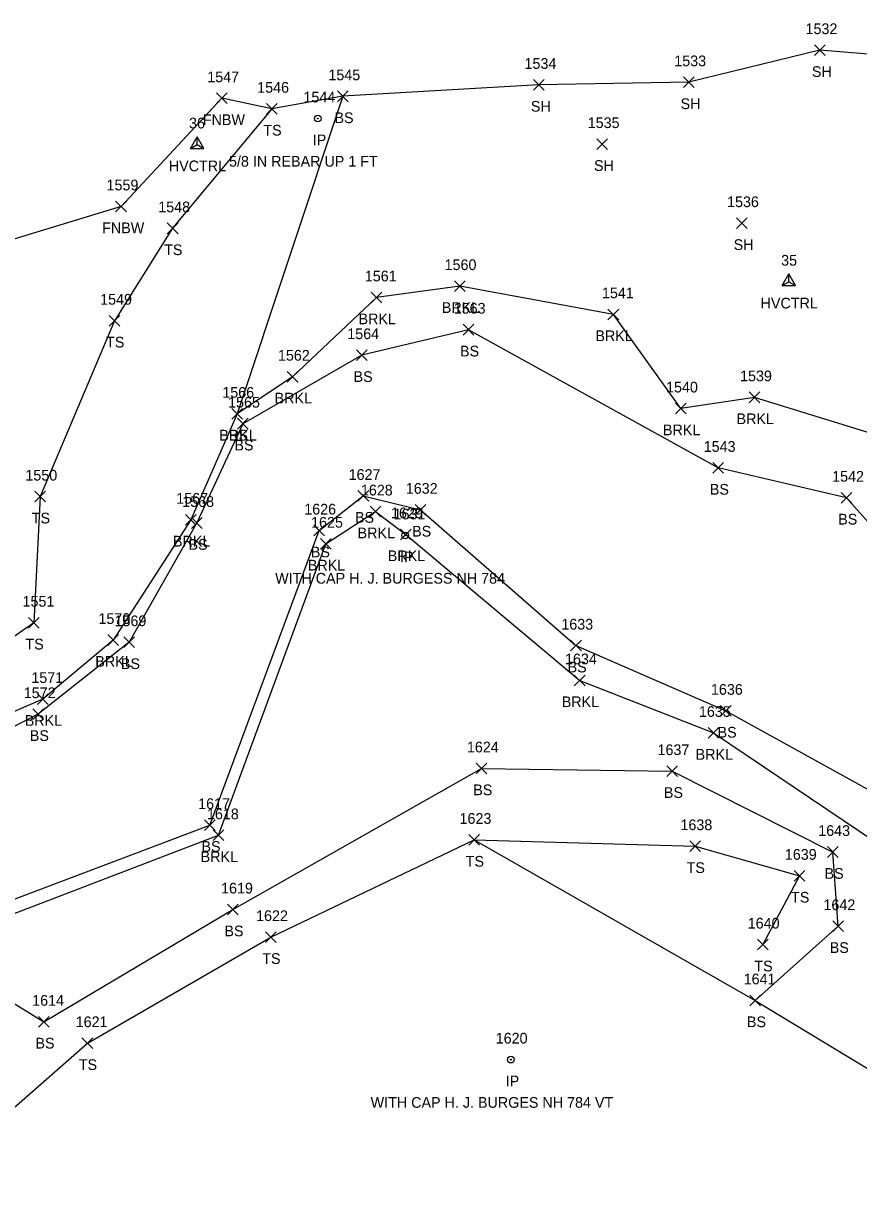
# Model space of a CAD drawing. Extents: x 1754529 to 1755810, y 621660 to 624656.
# Drawn here: x 1754679.8 to 1754836, y 624163.7 to 624380.7 of the extents above; entities that cross this region are included whole.
import ezdxf

# ---------------------------------------------------------------- set-up
doc = ezdxf.new("R2010")
doc.units = 0
for name, color, linetype in [('C_A', 7, 'Continuous'), ('C_I', 7, 'Continuous'), ('CPSM', 7, 'Continuous'), ('L_A', 7, 'Continuous'), ('L_I', 7, 'Continuous'), ('L_TIC', 7, 'Continuous'), ('LAWE', 7, 'Continuous'), ('LELB', 7, 'Continuous'), ('LSOGP', 7, 'Continuous'), ('M_A', 7, 'Continuous'), ('M_C', 7, 'Continuous'), ('M_I', 7, 'Continuous'), ('MPIR', 7, 'Continuous')]:
    doc.layers.add(name, color=color, linetype=linetype)

msp = doc.modelspace()

# ---------------------------------------------------------------- linework, layer by layer
at = {"layer": 'CPSM'}
for p, q in [((1754711.07, 624357.33), (1754712.32, 624359.5)), ((1754713.57, 624357.33), (1754712.32, 624359.5)), ((1754712.32, 624358.05), (1754712.32, 624359.5)), ((1754711.07, 624357.33), (1754712.32, 624358.05)), ((1754711.07, 624357.33), (1754713.57, 624357.33)), ((1754712.32, 624358.05), (1754712.32, 624358.05)), ((1754712.32, 624358.05), (1754713.57, 624357.33)), ((1754821.66, 624331.7), (1754822.91, 624333.86)), ((1754824.16, 624331.7), (1754822.91, 624333.86)), ((1754822.91, 624332.42), (1754822.91, 624333.86)), ((1754821.66, 624331.7), (1754822.91, 624332.42)), ((1754821.66, 624331.7), (1754824.16, 624331.7)), ((1754822.91, 624332.42), (1754822.91, 624332.42)), ((1754822.91, 624332.42), (1754824.16, 624331.7))]:
    msp.add_line(p, q, dxfattribs=at)
at = {"layer": 'L_TIC'}
for points in [[(1754827.7, 624374.67), (1754829.7, 624376.67)], [(1754829.7, 624374.67), (1754827.7, 624376.67)], [(1754775.19, 624368.18), (1754777.19, 624370.18)], [(1754777.19, 624368.18), (1754775.19, 624370.18)], [(1754803.17, 624368.67), (1754805.17, 624370.67)], [(1754805.17, 624368.67), (1754803.17, 624370.67)], [(1754738.54, 624366.05), (1754740.54, 624368.05)], [(1754740.54, 624366.05), (1754738.54, 624368.05)], [(1754715.91, 624365.68), (1754717.91, 624367.68)], [(1754717.91, 624365.68), (1754715.91, 624367.68)], [(1754725.29, 624363.72), (1754727.29, 624365.72)], [(1754727.29, 624363.72), (1754725.29, 624365.72)], [(1754786.99, 624357.12), (1754788.99, 624359.12)], [(1754788.99, 624357.12), (1754786.99, 624359.12)], [(1754697.09, 624345.48), (1754699.09, 624347.48)], [(1754699.09, 624345.48), (1754697.09, 624347.48)], [(1754813.09, 624342.35), (1754815.09, 624344.35)], [(1754815.09, 624342.35), (1754813.09, 624344.35)], [(1754706.74, 624341.39), (1754708.74, 624343.39)], [(1754708.74, 624341.39), (1754706.74, 624343.39)], [(1754760.39, 624330.59), (1754762.39, 624332.59)], [(1754762.39, 624330.59), (1754760.39, 624332.59)], [(1754744.82, 624328.48), (1754746.82, 624330.48)], [(1754746.82, 624328.48), (1754744.82, 624330.48)], [(1754789.09, 624325.32), (1754791.09, 624327.32)], [(1754791.09, 624325.32), (1754789.09, 624327.32)], [(1754695.89, 624324.13), (1754697.89, 624326.13)], [(1754697.89, 624324.13), (1754695.89, 624326.13)], [(1754762, 624322.46), (1754764, 624324.46)], [(1754764, 624322.46), (1754762, 624324.46)], [(1754742.11, 624317.69), (1754744.11, 624319.69)], [(1754744.11, 624317.69), (1754742.11, 624319.69)], [(1754729.15, 624313.67), (1754731.15, 624315.67)], [(1754731.15, 624313.67), (1754729.15, 624315.67)], [(1754815.47, 624309.82), (1754817.47, 624311.82)], [(1754817.47, 624309.82), (1754815.47, 624311.82)], [(1754801.72, 624307.73), (1754803.72, 624309.73)], [(1754803.72, 624307.73), (1754801.72, 624309.73)], [(1754718.81, 624306.75), (1754720.81, 624308.75)], [(1754720.81, 624306.75), (1754718.81, 624308.75)], [(1754718.81, 624306.75), (1754720.81, 624308.75)], [(1754720.81, 624306.75), (1754718.81, 624308.75)], [(1754719.84, 624304.9), (1754721.84, 624306.9)], [(1754721.84, 624304.9), (1754719.84, 624306.9)], [(1754808.68, 624296.64), (1754810.68, 624298.64)], [(1754810.68, 624296.64), (1754808.68, 624298.64)], [(1754682, 624291.27), (1754684, 624293.27)], [(1754684, 624291.27), (1754682, 624293.27)], [(1754742.37, 624291.4), (1754744.37, 624293.4)], [(1754744.37, 624291.4), (1754742.37, 624293.4)], [(1754832.67, 624291.06), (1754834.67, 624293.06)], [(1754834.67, 624291.06), (1754832.67, 624293.06)], [(1754744.66, 624288.49), (1754746.66, 624290.49)], [(1754746.66, 624288.49), (1754744.66, 624290.49)], [(1754753.05, 624288.81), (1754755.05, 624290.81)], [(1754755.05, 624288.81), (1754753.05, 624290.81)], [(1754710.15, 624286.95), (1754712.15, 624288.95)], [(1754712.15, 624286.95), (1754710.15, 624288.95)], [(1754711.27, 624286.35), (1754713.27, 624288.35)], [(1754713.27, 624286.35), (1754711.27, 624288.35)], [(1754734.12, 624284.93), (1754736.12, 624286.93)], [(1754736.12, 624284.93), (1754734.12, 624286.93)], [(1754750.29, 624284.22), (1754752.29, 624286.22)], [(1754752.29, 624284.22), (1754750.29, 624286.22)], [(1754735.35, 624282.47), (1754737.35, 624284.47)], [(1754737.35, 624282.47), (1754735.35, 624284.47)], [(1754680.82, 624267.72), (1754682.82, 624269.72)], [(1754682.82, 624267.72), (1754680.82, 624269.72)], [(1754695.65, 624264.49), (1754697.65, 624266.49)], [(1754697.65, 624264.49), (1754695.65, 624266.49)], [(1754698.63, 624264.07), (1754700.63, 624266.07)], [(1754700.63, 624264.07), (1754698.63, 624266.07)], [(1754782.11, 624263.44), (1754784.11, 624265.44)], [(1754784.11, 624263.44), (1754782.11, 624265.44)], [(1754782.8, 624256.95), (1754784.8, 624258.95)], [(1754784.8, 624256.95), (1754782.8, 624258.95)], [(1754682.46, 624253.46), (1754684.46, 624255.46)], [(1754684.46, 624253.46), (1754682.46, 624255.46)], [(1754810.13, 624251.26), (1754812.13, 624253.26)], [(1754812.13, 624251.26), (1754810.13, 624253.26)], [(1754681.61, 624250.63), (1754683.61, 624252.63)], [(1754683.61, 624250.63), (1754681.61, 624252.63)], [(1754807.82, 624247.13), (1754809.82, 624249.13)], [(1754809.82, 624247.13), (1754807.82, 624249.13)], [(1754764.47, 624240.5), (1754766.47, 624242.5)], [(1754766.47, 624240.5), (1754764.47, 624242.5)], [(1754800.09, 624240), (1754802.09, 624242)], [(1754802.09, 624240), (1754800.09, 624242)], [(1754713.68, 624229.92), (1754715.68, 624231.92)], [(1754715.68, 624229.92), (1754713.68, 624231.92)], [(1754715.32, 624228.01), (1754717.32, 624230.01)], [(1754717.32, 624228.01), (1754715.32, 624230.01)], [(1754763.09, 624227.15), (1754765.09, 624229.15)], [(1754765.09, 624227.15), (1754763.09, 624229.15)], [(1754804.37, 624225.97), (1754806.37, 624227.97)], [(1754806.37, 624225.97), (1754804.37, 624227.97)], [(1754830.12, 624224.89), (1754832.12, 624226.89)], [(1754832.12, 624224.89), (1754830.12, 624226.89)], [(1754830.12, 624224.89), (1754832.12, 624226.89)], [(1754832.12, 624224.89), (1754830.12, 624226.89)], [(1754823.89, 624220.44), (1754825.89, 624222.44)], [(1754825.89, 624220.44), (1754823.89, 624222.44)], [(1754717.97, 624214.14), (1754719.97, 624216.14)], [(1754719.97, 624214.14), (1754717.97, 624216.14)], [(1754831.09, 624211.03), (1754833.09, 624213.03)], [(1754833.09, 624211.03), (1754831.09, 624213.03)], [(1754725.07, 624208.99), (1754727.07, 624210.99)], [(1754727.07, 624208.99), (1754725.07, 624210.99)], [(1754817.03, 624207.59), (1754819.03, 624209.59)], [(1754819.03, 624207.59), (1754817.03, 624209.59)], [(1754815.61, 624197.17), (1754817.61, 624199.17)], [(1754817.61, 624197.17), (1754815.61, 624199.17)], [(1754682.66, 624193.18), (1754684.66, 624195.18)], [(1754684.66, 624193.18), (1754682.66, 624195.18)], [(1754690.8, 624189.17), (1754692.8, 624191.17)], [(1754692.8, 624189.17), (1754690.8, 624191.17)]]:
    msp.add_lwpolyline(points, dxfattribs=at)
at = {"layer": 'LAWE'}
for points in [[(1754841.35, 624303.13), (1754816.47, 624310.82), (1754802.72, 624308.73), (1754790.09, 624326.32), (1754761.39, 624331.59), (1754745.82, 624329.48), (1754730.15, 624314.67), (1754719.81, 624307.75), (1754711.15, 624287.95), (1754696.65, 624265.49), (1754683.46, 624254.46), (1754666.98, 624247.34), (1754629.31, 624266.44), (1754620.69, 624290.83), (1754593.02, 624292.79), (1754570.81, 624288.08), (1754549.59, 624279.71)], [(1754567.62, 624248.99), (1754580.83, 624255.32), (1754586.13, 624256.68), (1754607.14, 624241.98), (1754656.84, 624210.7), (1754674.02, 624212.83), (1754716.32, 624229.01), (1754736.35, 624283.47), (1754745.66, 624289.49), (1754751.29, 624285.22), (1754783.8, 624257.95), (1754808.82, 624248.13), (1754842.19, 624225.7)]]:
    msp.add_lwpolyline(points, dxfattribs=at)
at = {"layer": 'LELB'}
for points in [[(1754739.54, 624367.05), (1754719.81, 624307.75)], [(1754726.29, 624364.72), (1754707.74, 624342.39), (1754696.89, 624325.13), (1754683, 624292.27), (1754681.82, 624268.72), (1754664.01, 624256.32), (1754637.91, 624273.18), (1754633.66, 624291.71), (1754609.7, 624305.09)], [(1754851.86, 624271.62), (1754833.67, 624292.06), (1754809.68, 624297.64), (1754763, 624323.46), (1754743.11, 624318.69), (1754720.84, 624305.9), (1754712.27, 624287.35), (1754699.63, 624265.07), (1754682.61, 624251.63), (1754667.2, 624243.77)], [(1754672.66, 624215.04), (1754714.68, 624230.92), (1754735.12, 624285.93), (1754743.37, 624292.4), (1754754.05, 624289.81), (1754783.11, 624264.44), (1754811.13, 624252.26), (1754848.32, 624231.72)], [(1754656.84, 624210.7), (1754683.66, 624194.18), (1754718.97, 624215.14), (1754765.47, 624241.5), (1754801.09, 624241), (1754831.12, 624225.89)], [(1754691.8, 624190.17), (1754726.07, 624209.99), (1754764.09, 624228.15), (1754805.37, 624226.97), (1754824.89, 624221.44), (1754818.03, 624208.59)], [(1754816.61, 624198.17), (1754832.09, 624212.03), (1754831.12, 624225.89)]]:
    msp.add_lwpolyline(points, dxfattribs=at)
at = {"layer": 'LSOGP'}
for points in [[(1754853.48, 624373.62), (1754828.7, 624375.67), (1754804.17, 624369.67), (1754776.19, 624369.18), (1754739.54, 624367.05), (1754726.29, 624364.72), (1754716.91, 624366.68), (1754698.09, 624346.48), (1754676.6, 624339.95)], [(1754675.46, 624175.86), (1754691.8, 624190.17), (1754726.07, 624209.99), (1754764.09, 624228.15), (1754816.61, 624198.17), (1754873.5, 624163.73)]]:
    msp.add_lwpolyline(points, dxfattribs=at)
at = {"layer": 'MPIR'}
for centre, radius in [((1754734.87, 624362.91), 0.625), ((1754734.87, 624362.91), 0.0833), ((1754751.19, 624285.02), 0.625), ((1754751.19, 624285.02), 0.0833), ((1754770.93, 624187.11), 0.625), ((1754770.93, 624187.11), 0.0833)]:
    msp.add_circle(centre, radius, dxfattribs=at)

# ---------------------------------------------------------------- texts
at = {"layer": 'C_A'}
for p in [(1754707.02, 624353.05), (1754817.61, 624327.42)]:
    msp.add_text('HVCTRL', height=2, dxfattribs=at).set_placement(p)
at = {"layer": 'C_I'}
for s, p in [('36', (1754710.8, 624361.05)), ('35', (1754821.45, 624335.42))]:
    msp.add_text(s, height=2, dxfattribs=at).set_placement(p)
at = {"layer": 'L_A'}
for s, p in [('SH', (1754827.19, 624370.67)), ('SH', (1754774.68, 624364.18)), ('SH', (1754802.66, 624364.67)), ('FNBW', (1754713.38, 624361.68)), ('BS', (1754737.98, 624362.05)), ('TS', (1754724.69, 624359.72)), ('SH', (1754786.48, 624353.12)), ('FNBW', (1754694.56, 624341.48)), ('SH', (1754812.58, 624338.35)), ('TS', (1754706.15, 624337.39)), ('BRKL', (1754758.04, 624326.59)), ('BRKL', (1754742.47, 624324.48)), ('BRKL', (1754786.74, 624321.32)), ('TS', (1754695.3, 624320.13)), ('BS', (1754761.44, 624318.46)), ('BS', (1754741.55, 624313.69)), ('BRKL', (1754726.8, 624309.67)), ('BRKL', (1754813.11, 624305.82)), ('BRKL', (1754799.36, 624303.73)), ('BRKL', (1754716.46, 624302.75)), ('BS', (1754718.25, 624302.75)), ('BS', (1754719.28, 624300.9)), ('BS', (1754808.12, 624292.64)), ('TS', (1754681.41, 624287.27)), ('BS', (1754741.82, 624287.4)), ('BS', (1754832.11, 624287.06)), ('BRKL', (1754742.3, 624284.49)), ('BS', (1754752.49, 624284.81)), ('BRKL', (1754707.79, 624282.95)), ('BS', (1754710.71, 624282.35)), ('BS', (1754733.56, 624280.93)), ('BRKL', (1754747.94, 624280.22)), ('BRKL', (1754733, 624278.47)), ('TS', (1754680.23, 624263.72)), ('BRKL', (1754693.29, 624260.49)), ('BS', (1754698.07, 624260.07)), ('BS', (1754781.55, 624259.44)), ('BRKL', (1754780.45, 624252.95)), ('BRKL', (1754680.1, 624249.46)), ('BS', (1754681.05, 624246.63)), ('BS', (1754809.57, 624247.26)), ('BRKL', (1754805.47, 624243.13)), ('BS', (1754763.91, 624236.5)), ('BS', (1754799.53, 624236)), ('BS', (1754713.12, 624225.92)), ('BRKL', (1754712.97, 624224.01)), ('TS', (1754762.5, 624223.15)), ('TS', (1754803.78, 624221.97)), ('BS', (1754829.56, 624220.89)), ('BS', (1754829.56, 624220.89)), ('TS', (1754823.3, 624216.44)), ('BS', (1754717.41, 624210.14)), ('BS', (1754830.53, 624207.03)), ('TS', (1754724.48, 624204.99)), ('TS', (1754816.44, 624203.59)), ('BS', (1754815.05, 624193.17)), ('BS', (1754682.1, 624189.18)), ('TS', (1754690.21, 624185.17))]:
    msp.add_text(s, height=2, dxfattribs=at).set_placement(p)
at = {"layer": 'L_I'}
for s, p in [('1532', (1754826.01, 624378.67)), ('1533', (1754801.48, 624372.67)), ('1534', (1754773.5, 624372.18)), ('1547', (1754714.21, 624369.68)), ('1545', (1754736.84, 624370.05)), ('1546', (1754723.54, 624367.72)), ('1535', (1754785.3, 624361.12)), ('1559', (1754695.39, 624349.48)), ('1536', (1754811.34, 624346.35)), ('1548', (1754705.05, 624345.39)), ('1560', (1754758.56, 624334.59)), ('1561', (1754743.65, 624332.48)), ('1541', (1754787.96, 624329.32)), ('1549', (1754694.19, 624328.13)), ('1563', (1754760.26, 624326.46)), ('1564', (1754740.37, 624321.69)), ('1562', (1754727.41, 624317.67)), ('1539', (1754813.77, 624313.82)), ('1540', (1754799.94, 624311.73)), ('1566', (1754717.02, 624310.75)), ('1566', (1754717.02, 624310.75)), ('1565', (1754718.1, 624308.9)), ('1543', (1754806.98, 624300.64)), ('1550', (1754680.22, 624295.27)), ('1627', (1754740.63, 624295.4)), ('1542', (1754830.98, 624295.06)), ('1628', (1754742.92, 624292.49)), ('1632', (1754751.31, 624292.81)), ('1567', (1754708.41, 624290.95)), ('1568', (1754709.53, 624290.35)), ('1626', (1754732.33, 624288.93)), ('1629', (1754748.54, 624288.22)), ('1625', (1754733.61, 624286.47)), ('1551', (1754679.69, 624271.72)), ('1570', (1754693.87, 624268.49)), ('1569', (1754696.88, 624268.07)), ('1633', (1754780.37, 624267.44)), ('1634', (1754781.06, 624260.95)), ('1571', (1754681.33, 624257.46)), ('1636', (1754808.33, 624255.26)), ('1572', (1754679.92, 624254.63)), ('1635', (1754806.08, 624251.13)), ('1624', (1754762.73, 624244.5)), ('1637', (1754798.35, 624244)), ('1617', (1754712.51, 624233.92)), ('1618', (1754714.15, 624232.01)), ('1623', (1754761.35, 624231.15)), ('1638', (1754802.63, 624229.97)), ('1643', (1754828.38, 624228.89)), ('1643', (1754828.38, 624228.89)), ('1639', (1754822.14, 624224.44)), ('1619', (1754716.79, 624218.14)), ('1642', (1754829.35, 624215.03)), ('1622', (1754723.33, 624212.99)), ('1640', (1754815.2, 624211.59)), ('1641', (1754814.44, 624201.17)), ('1614', (1754681.49, 624197.18)), ('1621', (1754689.62, 624193.17))]:
    msp.add_text(s, height=2, dxfattribs=at).set_placement(p)
at = {"layer": 'M_A'}
for p in [(1754733.92, 624357.91), (1754750.24, 624280.02), (1754769.98, 624182.11)]:
    msp.add_text('IP', height=2, dxfattribs=at).set_placement(p)
at = {"layer": 'M_C'}
for s, p in [('5/8 IN REBAR UP 1 FT', (1754718.27, 624353.91)), ('WITH CAP H. J. BURGESS NH 784', (1754726.9, 624276.02)), ('WITH CAP H. J. BURGES NH 784 VT', (1754744.74, 624178.11))]:
    msp.add_text(s, height=2, dxfattribs=at).set_placement(p)
at = {"layer": 'M_I'}
for s, p in [('1544', (1754732.18, 624365.91)), ('1631', (1754749.02, 624288.02)), ('1620', (1754768.11, 624190.11))]:
    msp.add_text(s, height=2, dxfattribs=at).set_placement(p)

doc.saveas('drawing.dxf')
